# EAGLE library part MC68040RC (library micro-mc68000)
68xxx PROCESSOR
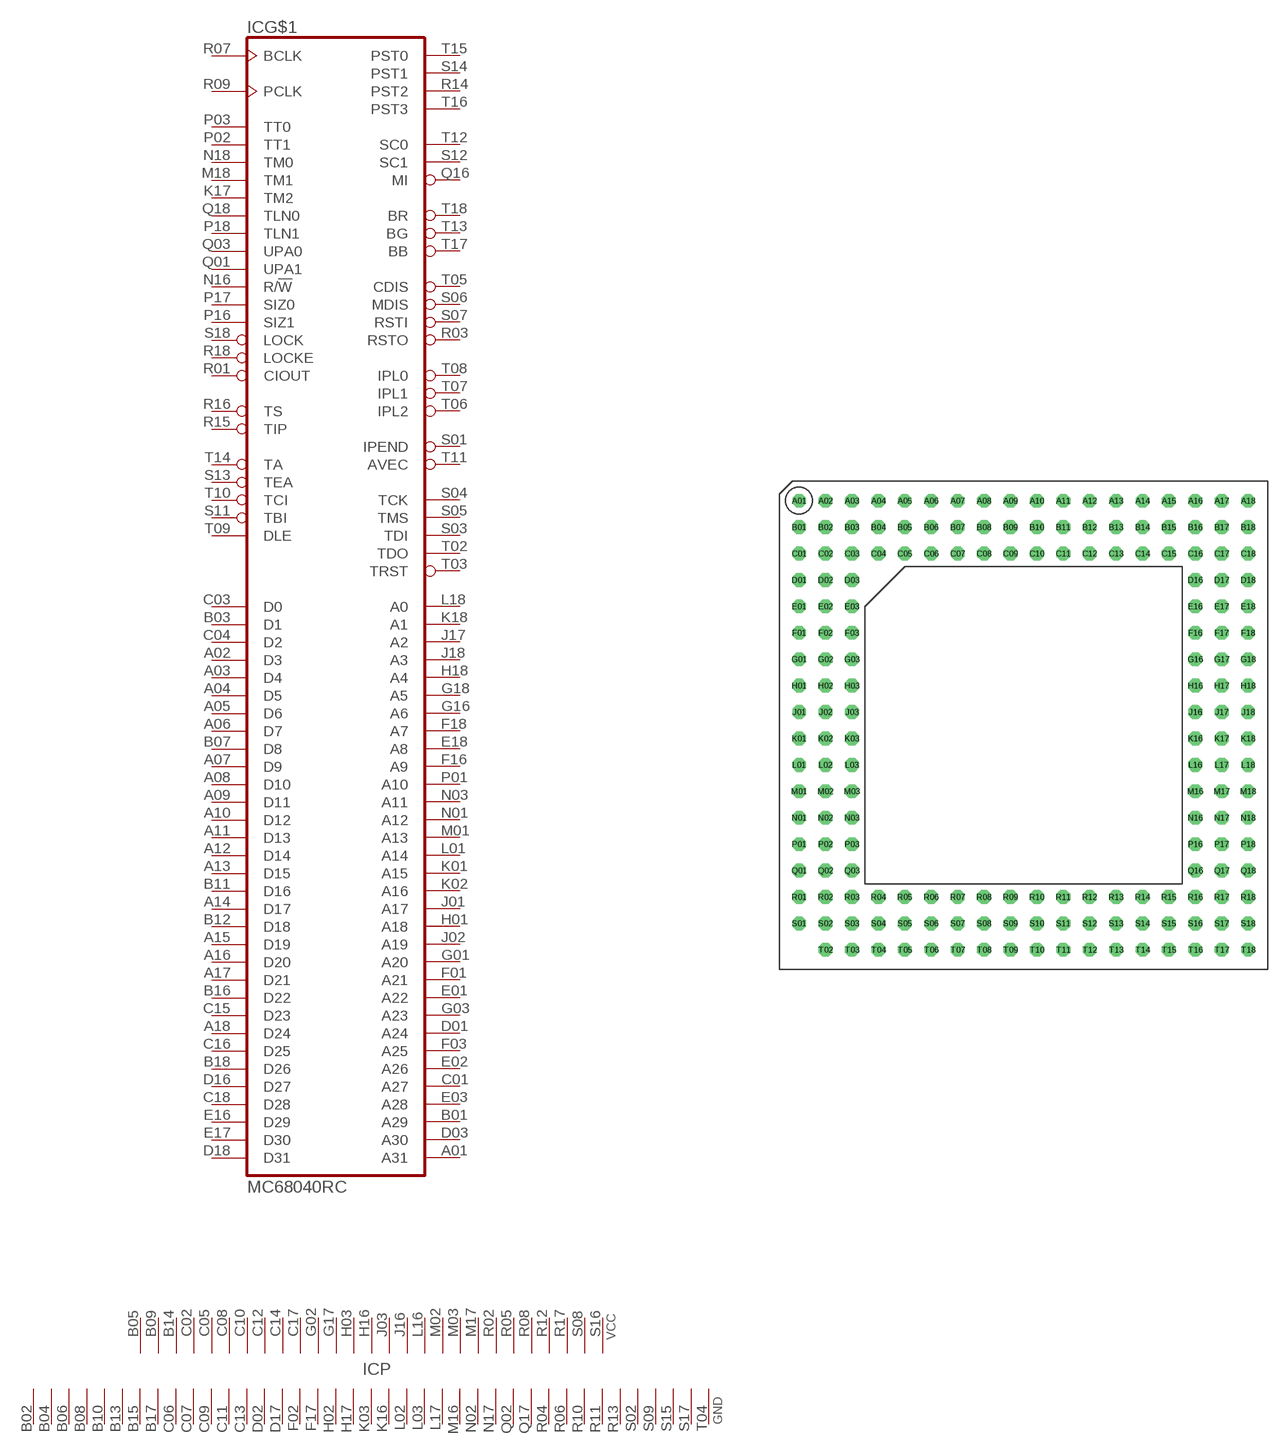
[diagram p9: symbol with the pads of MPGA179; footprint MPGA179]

Designator prefix IC; gates G$1=68040 P=27PW39GN

## MC68040RC (MF: MOTOROLA; MPN: MC68040RC40A; OC_FARNELL: 1579784; OC_NEWARK: 24C6756)  [MPGA179]
A01  G$1:A31  out
A02  G$1:D3
A03  G$1:D4
A04  G$1:D5
A05  G$1:D6
A06  G$1:D7
A07  G$1:D9
A08  G$1:D10
A09  G$1:D11
A10  G$1:D12
A11  G$1:D13
A12  G$1:D14
A13  G$1:D15
A14  G$1:D17
A15  G$1:D19
A16  G$1:D20
A17  G$1:D21
A18  G$1:D24
B01  G$1:A29  out
B02  P:GND  pwr
B03  G$1:D1
B04  P:GND  pwr
B05  P:VCC  pwr
B06  P:GND  pwr
B07  G$1:D8
B08  P:GND  pwr
B09  P:VCC  pwr
B10  P:GND  pwr
B11  G$1:D16
B12  G$1:D18
B13  P:GND  pwr
B14  P:VCC  pwr
B15  P:GND  pwr
B16  G$1:D22
B17  P:GND  pwr
B18  G$1:D26
C01  G$1:A27  out
C02  P:VCC  pwr
C03  G$1:D0
C04  G$1:D2
C05  P:VCC  pwr
C06  P:GND  pwr
C07  P:GND  pwr
C08  P:VCC  pwr
C09  P:GND  pwr
C10  P:VCC  pwr
C11  P:GND  pwr
C12  P:VCC  pwr
C13  P:GND  pwr
C14  P:VCC  pwr
C15  G$1:D23
C16  G$1:D25
C17  P:VCC  pwr
C18  G$1:D28
D01  G$1:A24  out
D02  P:GND  pwr
D03  G$1:A30  out
D16  G$1:D27
D17  P:GND  pwr
D18  G$1:D31
E01  G$1:A22  out
E02  G$1:A26  out
E03  G$1:A28  out
E16  G$1:D29
E17  G$1:D30
E18  G$1:A8  out
F01  G$1:A21  out
F02  P:GND  pwr
F03  G$1:A25  out
F16  G$1:A9  out
F17  P:GND  pwr
F18  G$1:A7  out
G01  G$1:A20  out
G02  P:VCC  pwr
G03  G$1:A23  out
G16  G$1:A6  out
G17  P:VCC  pwr
G18  G$1:A5  out
H01  G$1:A18  out
H02  P:GND  pwr
H03  P:VCC  pwr
H16  P:VCC  pwr
H17  P:GND  pwr
H18  G$1:A4  out
J01  G$1:A17  out
J02  G$1:A19  out
J03  P:VCC  pwr
J16  P:VCC  pwr
J17  G$1:A2  out
J18  G$1:A3  out
K01  G$1:A15  out
K02  G$1:A16  out
K03  P:GND  pwr
K16  P:GND  pwr
K17  G$1:TM2  out
K18  G$1:A1  out
L01  G$1:A14  out
L02  P:GND  pwr
L03  P:GND  pwr
L16  P:VCC  pwr
L17  P:GND  pwr
L18  G$1:A0  out
M01  G$1:A13  out
M02  P:VCC  pwr
M03  P:VCC  pwr
M16  P:GND  pwr
M17  P:VCC  pwr
M18  G$1:TM1  out
N01  G$1:A12  out
N02  P:GND  pwr
N03  G$1:A11  out
N16  G$1:R/!W
N17  P:GND  pwr
N18  G$1:TM0  out
P01  G$1:A10  out
P02  G$1:TT1
P03  G$1:TT0
P16  G$1:SIZ1
P17  G$1:SIZ0
P18  G$1:TLN1  out
Q01  G$1:UPA1  out
Q02  P:GND  pwr
Q03  G$1:UPA0  out
Q16  G$1:MI  out
Q17  P:GND  pwr
Q18  G$1:TLN0  out
R01  G$1:CIOUT  out
R02  P:VCC  pwr
R03  G$1:RSTO  out
R04  P:GND  pwr
R05  P:VCC  pwr
R06  P:GND  pwr
R07  G$1:BCLK  in
R08  P:VCC  pwr
R09  G$1:PCLK  in
R10  P:GND  pwr
R11  P:GND  pwr
R12  P:VCC  pwr
R13  P:GND  pwr
R14  G$1:PST2  out
R15  G$1:TIP  out
R16  G$1:TS
R17  P:VCC  pwr
R18  G$1:LOCKE  out
S01  G$1:IPEND  out
S02  P:GND  pwr
S03  G$1:TDI  in
S04  G$1:TCK  in
S05  G$1:TMS  in
S06  G$1:MDIS  in
S07  G$1:RSTI  in
S08  P:VCC  pwr
S09  P:GND  pwr
S11  G$1:TBI  in
S12  G$1:SC1  in
S13  G$1:TEA  in
S14  G$1:PST1  out
S15  P:GND  pwr
S16  P:VCC  pwr
S17  P:GND  pwr
S18  G$1:LOCK  out
T02  G$1:TDO  out
T03  G$1:TRST  in
T04  P:GND  pwr
T05  G$1:CDIS  in
T06  G$1:IPL2  in
T07  G$1:IPL1  in
T08  G$1:IPL0  in
T09  G$1:DLE  in
T10  G$1:TCI  in
T11  G$1:AVEC  in
T12  G$1:SC0  in
T13  G$1:BG  in
T14  G$1:TA
T15  G$1:PST0  out
T16  G$1:PST3  out
T17  G$1:BB
T18  G$1:BR  out

## Footprint MPGA179 (pad centres in mm)
micro Ball Grid Array
drill 0.813 octagon: A01 -21.59,21.59; A02 -19.05,21.59; A03 -16.51,21.59; A04 -13.97,21.59; A05 -11.43,21.59; A06 -8.89,21.59; A07 -6.35,21.59; A08 -3.81,21.59; A09 -1.27,21.59; A10 1.27,21.59; A11 3.81,21.59; A12 6.35,21.59; A13 8.89,21.59; A14 11.43,21.59; A15 13.97,21.59; A16 16.51,21.59; A17 19.05,21.59; A18 21.59,21.59; B01 -21.59,19.05; B02 -19.05,19.05; B03 -16.51,19.05; B04 -13.97,19.05; B05 -11.43,19.05; B06 -8.89,19.05; B07 -6.35,19.05; B08 -3.81,19.05; B09 -1.27,19.05; B10 1.27,19.05; B11 3.81,19.05; B12 6.35,19.05; B13 8.89,19.05; B14 11.43,19.05; B15 13.97,19.05; B16 16.51,19.05; B17 19.05,19.05; B18 21.59,19.05; C01 -21.59,16.51; C02 -19.05,16.51; C03 -16.51,16.51; C04 -13.97,16.51; C05 -11.43,16.51; C06 -8.89,16.51; C07 -6.35,16.51; C08 -3.81,16.51; C09 -1.27,16.51; C10 1.27,16.51; C11 3.81,16.51; C12 6.35,16.51; C13 8.89,16.51; C14 11.43,16.51; C15 13.97,16.51; C16 16.51,16.51; C17 19.05,16.51; C18 21.59,16.51; D01 -21.59,13.97; D02 -19.05,13.97; D03 -16.51,13.97; D16 16.51,13.97; D17 19.05,13.97; D18 21.59,13.97; E01 -21.59,11.43; E02 -19.05,11.43; E03 -16.51,11.43; E16 16.51,11.43; E17 19.05,11.43; E18 21.59,11.43; F01 -21.59,8.89; F02 -19.05,8.89; F03 -16.51,8.89; F16 16.51,8.89; F17 19.05,8.89; F18 21.59,8.89; G01 -21.59,6.35; G02 -19.05,6.35; G03 -16.51,6.35; G16 16.51,6.35; G17 19.05,6.35; G18 21.59,6.35; H01 -21.59,3.81; H02 -19.05,3.81; H03 -16.51,3.81; H16 16.51,3.81; H17 19.05,3.81; H18 21.59,3.81; J01 -21.59,1.27; J02 -19.05,1.27; J03 -16.51,1.27; J16 16.51,1.27; J17 19.05,1.27; J18 21.59,1.27; K01 -21.59,-1.27; K02 -19.05,-1.27; K03 -16.51,-1.27; K16 16.51,-1.27; K17 19.05,-1.27; K18 21.59,-1.27; L01 -21.59,-3.81; L02 -19.05,-3.81; L03 -16.51,-3.81; L16 16.51,-3.81; L17 19.05,-3.81; L18 21.59,-3.81; M01 -21.59,-6.35; M02 -19.05,-6.35; M03 -16.51,-6.35; M16 16.51,-6.35; M17 19.05,-6.35; M18 21.59,-6.35; N01 -21.59,-8.89; N02 -19.05,-8.89; N03 -16.51,-8.89; N16 16.51,-8.89; N17 19.05,-8.89; N18 21.59,-8.89; P01 -21.59,-11.43; P02 -19.05,-11.43; P03 -16.51,-11.43; P16 16.51,-11.43; P17 19.05,-11.43; P18 21.59,-11.43; Q01 -21.59,-13.97; Q02 -19.05,-13.97; Q03 -16.51,-13.97; Q16 16.51,-13.97; Q17 19.05,-13.97; Q18 21.59,-13.97; R01 -21.59,-16.51; R02 -19.05,-16.51; R03 -16.51,-16.51; R04 -13.97,-16.51; R05 -11.43,-16.51; R06 -8.89,-16.51; R07 -6.35,-16.51; R08 -3.81,-16.51; R09 -1.27,-16.51; R10 1.27,-16.51; R11 3.81,-16.51; R12 6.35,-16.51; R13 8.89,-16.51; R14 11.43,-16.51; R15 13.97,-16.51; R16 16.51,-16.51; R17 19.05,-16.51; R18 21.59,-16.51; S01 -21.59,-19.05; S02 -19.05,-19.05; S03 -16.51,-19.05; S04 -13.97,-19.05; S05 -11.43,-19.05; S06 -8.89,-19.05; S07 -6.35,-19.05; S08 -3.81,-19.05; S09 -1.27,-19.05; S10 1.27,-19.05; S11 3.81,-19.05; S12 6.35,-19.05; S13 8.89,-19.05; S14 11.43,-19.05; S15 13.97,-19.05; S16 16.51,-19.05; S17 19.05,-19.05; S18 21.59,-19.05; T02 -19.05,-21.59; T03 -16.51,-21.59; T04 -13.97,-21.59; T05 -11.43,-21.59; T06 -8.89,-21.59; T07 -6.35,-21.59; T08 -3.81,-21.59; T09 -1.27,-21.59; T10 1.27,-21.59; T11 3.81,-21.59; T12 6.35,-21.59; T13 8.89,-21.59; T14 11.43,-21.59; T15 13.97,-21.59; T16 16.51,-21.59; T17 19.05,-21.59; T18 21.59,-21.59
